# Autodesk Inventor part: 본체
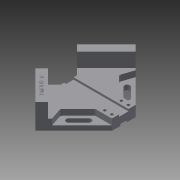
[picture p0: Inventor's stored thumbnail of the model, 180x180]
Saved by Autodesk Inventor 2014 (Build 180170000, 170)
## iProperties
Created: 2019-04
Part Number: 본체
Material: Generic
Document SubType Name: Modeling
Designer: kh
Density: 1 g/cm^3
Appearance: Default
Author: kh
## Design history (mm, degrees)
sketch "Sketch1"
  geometry: L1 (0, 47.99)-(0, -172.536); L2 (0, 0)-(-14.005, 0); L3 (-14.005, 0)-(-35.355, 21.35); L4 (-35.355, 21.35)-(-84.853, -28.147); L5 (-84.853, -28.147)-(-20, -93); L6 (-20, -93)-(0, -93); L7 (-35.355, 21.35)-(0, 56.706); L8 (-20, -93)-(0, -113); L9 (0, 0)-(14.005, 0); L10 (14.005, 0)-(35.355, 21.35); L11 (35.355, 21.35)-(84.853, -28.147); L12 (84.853, -28.147)-(20, -93); L13 (20, -93)-(0, -93); L14 (35.355, 21.35)-(0, 56.706); L15 (20, -93)-(0, -113); 1 further point
  constraints: 30 end point, 6 point on line, 4 perpendicular, 4 symmetric about line, 1 collinear, 1 parallel, 1 vertical
  dimensions: "d0" = 50 distance of L3.end L7.end; "d1" = 120 distance of L7.end L4.end; "d2" = 120 distance of L8.end L4.end; "d3" = 20 horizontal distance of L8.end L5.end; "d4" = 93 distance of L6.end L2.start
extrude "Extrusion1" new body sketch "Sketch1" distance "d5" = 18; taper "d6" = 0 deg
sketch "Sketch2"
  geometry: L1 (-35.355, 21.35)-(-84.853, -28.147) reference; L2 (-14.005, 0)-(-35.355, 21.35) reference; L3 (-35.355, 21.35)-(-84.853, -28.147); L4 (-74.246, -38.754)-(-24.749, 10.744); L5 (-35.355, 21.35)-(-24.749, 10.744); L6 (-84.853, -28.147)-(-20, -93) reference; L7 (-84.853, -28.147)-(-74.246, -38.754); 1 further point
  constraints: 8 end point, 3 collinear, 1 perpendicular, 1 point on line
  dimensions: "d7" = 15 distance of L1.start L4.end
extrude "Extrusion2" join sketch "Sketch2" distance "d8" = 24; taper "d9" = 0 deg
mirror "Mirror1"
sketch "Sketch3"
  geometry: L1 (-8, 0)-(8, 0); L2 (8, 0)-(8, -93); L3 (8, -93)-(-8, -93); L4 (-8, -93)-(-8, 0); L5 (14.005, 0)-(-14.005, 0) reference; L6 (-20, -93)-(20, -93) reference; 3 further points
  constraints: 8 end point, 4 midpoint, 2 parallel, 1 horizontal, 1 perpendicular
  dimensions: "d10" = 16 distance of L1.start L1.end
extrude "Extrusion3" cut sketch "Sketch3" distance "d11" = 3.5; taper "d12" = 0 deg
sketch "Sketch4"
  geometry: L1 (-6, 0)-(6, 0); L2 (6, 0)-(6, -93); L3 (6, -93)-(-6, -93); L4 (-6, -93)-(-6, 0); L5 (-14.005, 0)-(14.005, 0) reference; L6 (20, -93)-(-20, -93) reference; 3 further points
  constraints: 8 end point, 4 midpoint, 2 parallel, 1 horizontal, 1 perpendicular
  dimensions: "d13" = 12 distance of L1.start L1.end
extrude "Extrusion4" cut sketch "Sketch4" distance "d14" = 3; taper "d15" = 0 deg
sketch "Sketch5"
  geometry: L1 (-74.246, -38.754)-(-20, -93) reference; L2 (-49.497, -35.218)-(-20, -64.716); L3 (-67.175, -31.683)-(-12.929, -85.929); L4 (-49.497, -49.36)-(-32.527, -66.331); L5 (-52.679, -52.542)-(-35.709, -69.513); L6 (-29.345, -63.149)-(-46.315, -46.178); L7 (-35.355, 21.35)-(-84.853, -28.147) reference; L8 (-70.711, -42.289)-(-49.497, -35.218); L9 (-20, -93)-(-20, -64.716); L10 (-70.711, -42.289)-(-20, -93); A1 r 4.5 centre (-49.497, -49.36) between (-46.315, -46.178) and (-52.679, -52.542); A2 r 4.5 centre (-32.527, -66.331) between (-35.709, -69.513) and (-29.345, -63.149); 2 further points
  constraints: 18 end point, 4 point on circle, 4 tangent, 3 parallel, 3 point on line, 2 centre point, 1 collinear, 1 midpoint, 1 vertical
  dimensions: "d16" = 20 distance between parallel lines of L1 L2; "d17" = 10 distance between parallel lines of L1 L3; "d19" = 24 distance of L4.end L4.start; "d20" = 40 distance from line of L4.start L7; "d22" = 20 distance from line of L8.start L7; "d23" = 30 distance from line of L2.start L7; "d24" = 9 diameter of A2
extrude "Extrusion5" cut sketch "Sketch5" distance "d25" = 10; taper "d26" = 0 deg
extrude "Extrusion6" cut sketch "Sketch5" stored distance "d27" = 10; taper "d28" = 0 deg
mirror "Mirror2"
mirror "Mirror3"
sketch "Sketch7"
  geometry: L1 (-8, -93)-(-20, -93) reference; 3 further points
  dimensions: "d32" = 6 distance from line of L1 point (-14, -87); "d33" = 12 distance of point (-14, -87) point (-14, -75); "d34" = 14 horizontal distance of point (0, 0) point (-14, -87); "d35" = 14 horizontal distance of point (0, 0) point (-14, -75)
hole "Hole1" sketch "Sketch7" at (-14, -75), (-14, -87) diameter "d36" = 4.5; stored, may be unused: countersink angle "d40" = 90 deg, drill point angle "d42" = 118 deg; dims "d37" = 6, "d38" = 8, "d39" = 10, "d41" = 8
mirror "Mirror4"
sketch "Sketch8"
  geometry: L1 (-35.829, 1.657)-(-65.159, -27.673); L2 (-65.159, -27.673)-(-73.772, -19.06); L3 (-73.772, -19.06)-(-44.442, 10.27); L4 (-44.442, 10.27)-(-35.829, 1.657); L5 (-35.355, 21.35)-(-84.853, -28.147) reference; L6 (-35.829, 1.657)-(-73.772, -19.06); L7 (-14.005, 0)-(-24.749, 10.744) reference; 2 further points
  constraints: 2 end point, 1 midpoint, 1 parallel, 2 other
  dimensions: "d43" = 35 distance from line of point (-54.801, -8.702) L7; "d44" = 7.5 distance from line of L5 point (-54.801, -8.702)
emboss "Emboss1" sketch "Sketch8" dims "d45" = 0.5, "d46" = 0
fillet "Fillet1" dims "d47" = 5
body "Solid1"
